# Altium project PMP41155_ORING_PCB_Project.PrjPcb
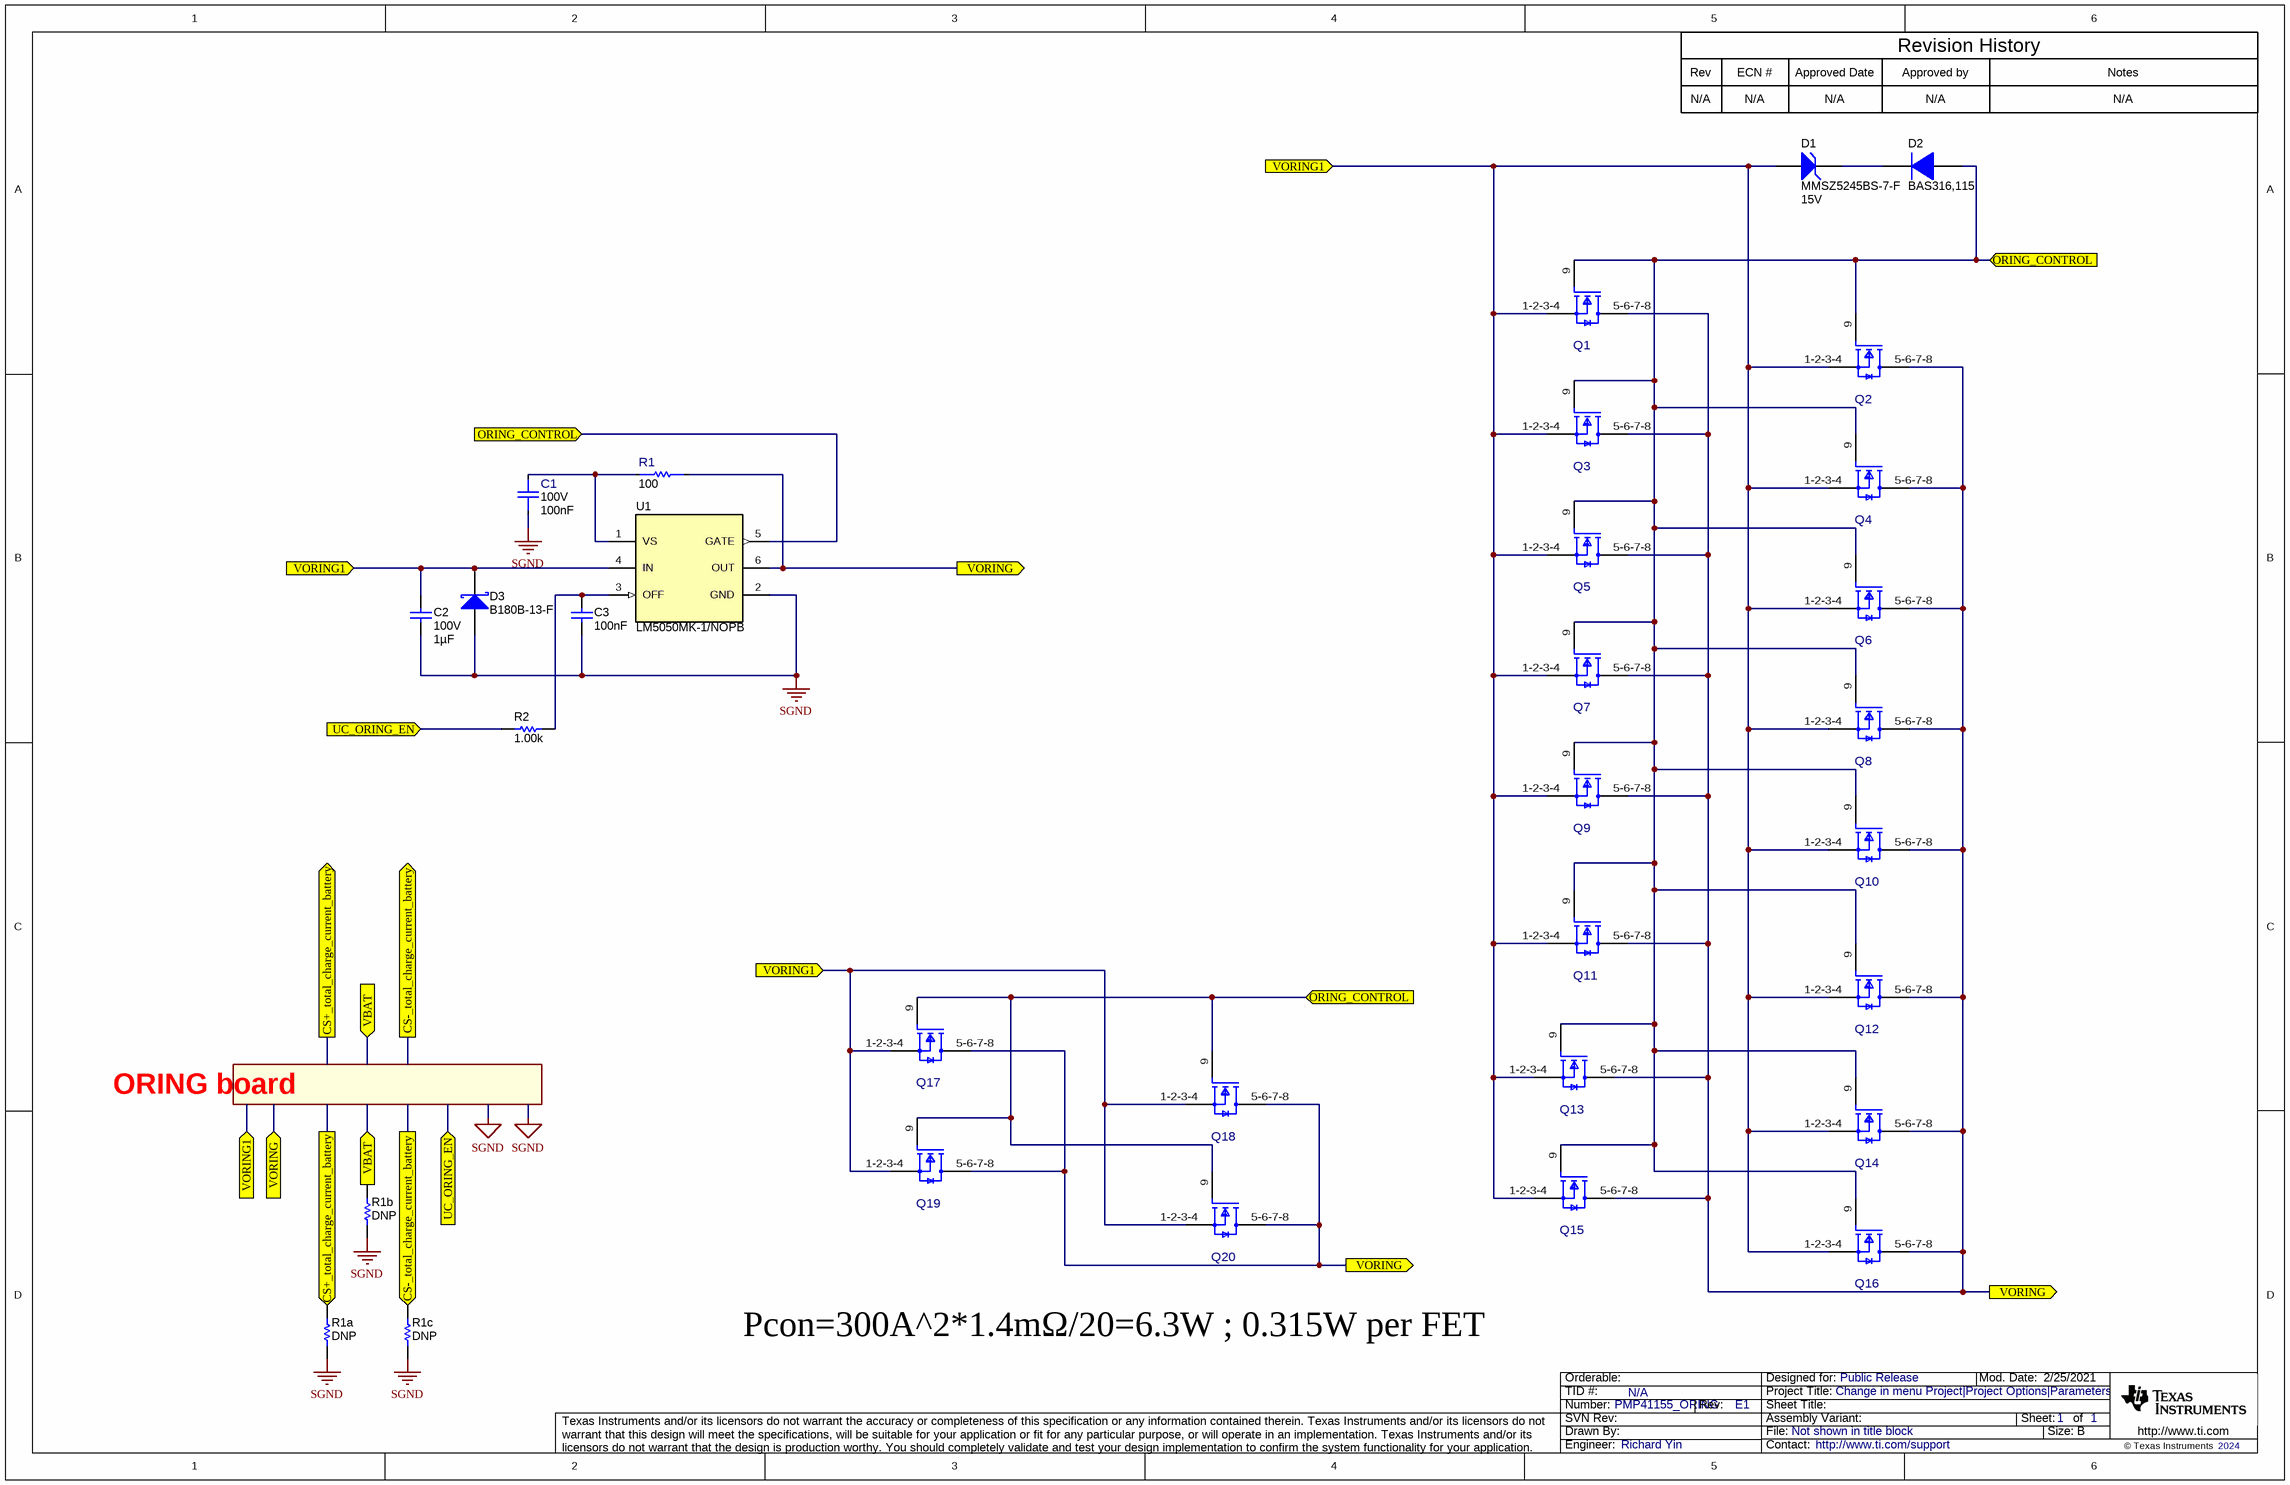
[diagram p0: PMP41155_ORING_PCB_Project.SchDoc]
CopyrightYear: 2024; PCB_Layout: Richard Yin; PCB_Rev: E1; PRJ_Customer: Public Release; PRJ_Engineer: Richard Yin; PRJ_Number: PMP41155_ORING; PRJ_Title: Change in menu Project|Project Options|Parameters; SCH_Rev: E1; TechSupport: http://www.ti.com/support; TID: N/A
1 sheet, 32 parts. Net scope: flat (ports and power ports of the same name join across sheets).
Board file: PMP41155_ORING_PCB_Project.PcbDoc

## Sheet PMP41155_ORING_PCB_Project.SchDoc
size 431 x 279 mm; Date: Not shown in title block; ApprovedBy: Not shown in title block; CheckedBy: Not shown in title block; Author: Not shown in title block; CompanyName: Not shown in title block; Engineer: Not shown in title block; Organization: Not shown in title block; Address1: Not shown in title block; Address2: Not shown in title block; Address3: Not shown in title block; Address4: Not shown in title block; DocumentNumber: 1; Revision: Use project parameter SCH_Rev; SheetNumber: 1; SheetTotal: 1; PageSetup: Record=PageOptions¦CenterHorizontal=True¦CenterVertical=True¦PrintScale=1.00¦XCorrection=1.00¦YCorrection=1.00¦PrintKind=0¦BorderSize=5000000¦LeftOffset=0¦BottomOffset=0¦Orientation=2¦PaperLength=1000¦PaperWidth=1000¦Scale=100¦PaperSource=15¦PrintQuality=600¦MediaType=1¦DitherType=10¦PaperKind=Letter¦PrintScaleMode=1

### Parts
C1  VDC_V: 100V  Cap_F: 100nF  [FP-885012206120_0603-MFG]  (hidden comment: 885012206120)
C2  VDC_V: 100V  Cap_F: 1µF  [0805_150]  (hidden comment: KAF21KR72A105KU)
C3  Cap_F: 100nF  [0603]  (hidden comment: GRM188R71E104KA01D)
D1  MMSZ5245BS-7-F  value 15V  [SOD-323]
D2  BAS316,115  [SOD-323]
D3  B180B-13-F  [SMB]
Q1  IQD016N08NM5CGATMA1  [FP-IQD016N08NM5CGATMA1_TTFN-9-MFG]  (value not drawn)
Q2  IQD016N08NM5CGATMA1  [FP-IQD016N08NM5CGATMA1_TTFN-9-MFG]  (value not drawn)
Q3  IQD016N08NM5CGATMA1  [FP-IQD016N08NM5CGATMA1_TTFN-9-MFG]  (value not drawn)
Q4  IQD016N08NM5CGATMA1  [FP-IQD016N08NM5CGATMA1_TTFN-9-MFG]  (value not drawn)
Q5  IQD016N08NM5CGATMA1  [FP-IQD016N08NM5CGATMA1_TTFN-9-MFG]  (value not drawn)
Q6  IQD016N08NM5CGATMA1  [FP-IQD016N08NM5CGATMA1_TTFN-9-MFG]  (value not drawn)
Q7  IQD016N08NM5CGATMA1  [FP-IQD016N08NM5CGATMA1_TTFN-9-MFG]  (value not drawn)
Q8  IQD016N08NM5CGATMA1  [FP-IQD016N08NM5CGATMA1_TTFN-9-MFG]  (value not drawn)
Q9  IQD016N08NM5CGATMA1  [FP-IQD016N08NM5CGATMA1_TTFN-9-MFG]  (value not drawn)
Q10  IQD016N08NM5CGATMA1  [FP-IQD016N08NM5CGATMA1_TTFN-9-MFG]  (value not drawn)
Q11  IQD016N08NM5CGATMA1  [FP-IQD016N08NM5CGATMA1_TTFN-9-MFG]  (value not drawn)
Q12  IQD016N08NM5CGATMA1  [FP-IQD016N08NM5CGATMA1_TTFN-9-MFG]  (value not drawn)
Q13  IQD016N08NM5CGATMA1  [FP-IQD016N08NM5CGATMA1_TTFN-9-MFG]  (value not drawn)
Q14  IQD016N08NM5CGATMA1  [FP-IQD016N08NM5CGATMA1_TTFN-9-MFG]  (value not drawn)
Q15  IQD016N08NM5CGATMA1  [FP-IQD016N08NM5CGATMA1_TTFN-9-MFG]  (value not drawn)
Q16  IQD016N08NM5CGATMA1  [FP-IQD016N08NM5CGATMA1_TTFN-9-MFG]  (value not drawn)
Q17  IQD016N08NM5CGATMA1  [FP-IQD016N08NM5CGATMA1_TTFN-9-MFG]  (value not drawn)
Q18  IQD016N08NM5CGATMA1  [FP-IQD016N08NM5CGATMA1_TTFN-9-MFG]  (value not drawn)
Q19  IQD016N08NM5CGATMA1  [FP-IQD016N08NM5CGATMA1_TTFN-9-MFG]  (value not drawn)
Q20  IQD016N08NM5CGATMA1  [FP-IQD016N08NM5CGATMA1_TTFN-9-MFG]  (value not drawn)
R1  value 100  [FP-RMCF0402FT100R_0402-MFG]  (hidden comment: RMCF0402FT100R)
R1a  ValueDisplayed: DNP  [0402]  (hidden comment: MCR01MZPF1001)
R1b  ValueDisplayed: DNP  [0402]  (hidden comment: MCR01MZPF1001)
R1c  ValueDisplayed: DNP  [0402]  (hidden comment: MCR01MZPF1001)
R2  ValueDisplayed: 1.00k  [0402]  (hidden comment: MCR01MZPF1001)
U1  LM5050MK-1/NOPB  [DDC0006A_N]

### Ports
CS+_total_charge_current_battery (out), CS-_total_charge_current_battery (out), ORING_CONTROL (in), UC_ORING_EN (in), VBAT (in), VORING1 (in), VORING (in), VORING (out)

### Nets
SGND: C1.1 C2.2 C3.2 D3.2(A) R1a.1 R1b.1 R1c.1 U1.2(GND)
CS+_total_charge_current_battery: R1a.2 ; port CS+_total_charge_current_battery
CS-_total_charge_current_battery: R1c.2 ; port CS-_total_charge_current_battery
ORING_CONTROL: D2.2(A) Q1.9(Gate) Q2.9(Gate) Q3.9(Gate) Q4.9(Gate) Q5.9(Gate) Q6.9(Gate) Q7.9(Gate) Q8.9(Gate) Q9.9(Gate) Q10.9(Gate) Q11.9(Gate) Q12.9(Gate) Q13.9(Gate) Q14.9(Gate) Q15.9(Gate) Q16.9(Gate) Q17.9(Gate) Q18.9(Gate) Q19.9(Gate) Q20.9(Gate) U1.5(GATE) ; port ORING_CONTROL
UC_ORING_EN: R2.1 ; port UC_ORING_EN
VBAT: R1b.2 ; port VBAT
VORING: Q1.5-6-7-8(Drain) Q2.5-6-7-8(Drain) Q3.5-6-7-8(Drain) Q4.5-6-7-8(Drain) Q5.5-6-7-8(Drain) Q6.5-6-7-8(Drain) Q7.5-6-7-8(Drain) Q8.5-6-7-8(Drain) Q9.5-6-7-8(Drain) Q10.5-6-7-8(Drain) Q11.5-6-7-8(Drain) Q12.5-6-7-8(Drain) Q13.5-6-7-8(Drain) Q14.5-6-7-8(Drain) Q15.5-6-7-8(Drain) Q16.5-6-7-8(Drain) Q17.5-6-7-8(Drain) Q18.5-6-7-8(Drain) Q19.5-6-7-8(Drain) Q20.5-6-7-8(Drain) R1.2 U1.6(OUT) ; port VORING
VORING1: C2.1 D1.2(A) D3.1(K) Q1.1-2-3-4(Source) Q2.1-2-3-4(Source) Q3.1-2-3-4(Source) Q4.1-2-3-4(Source) Q5.1-2-3-4(Source) Q6.1-2-3-4(Source) Q7.1-2-3-4(Source) Q8.1-2-3-4(Source) Q9.1-2-3-4(Source) Q10.1-2-3-4(Source) Q11.1-2-3-4(Source) Q12.1-2-3-4(Source) Q13.1-2-3-4(Source) Q14.1-2-3-4(Source) Q15.1-2-3-4(Source) Q16.1-2-3-4(Source) Q17.1-2-3-4(Source) Q18.1-2-3-4(Source) Q19.1-2-3-4(Source) Q20.1-2-3-4(Source) U1.4(IN) ; port VORING1
NetC1_2: C1.2 R1.1 U1.1(VS)
NetC3_1: C3.1 R2.2 U1.3(OFF)
NetD1_1: D1.1(K) D2.1(K)

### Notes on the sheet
- Rev
- N/A
- ECN #
- Approved Date
- Approved by
- Revision History
- Notes
- ORING board
- Pcon=300A^2*1.4mΩ/20=6.3W ; 0.315W per FET

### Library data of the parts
C1 = CMP-0097294-1: 0.1 µF ±10% 100V Ceramic Capacitor X7R 0603 (1608 Metric); Manufacturer: Wurth Electronics; TempCo: 15%; SizeZ_mm: 0.87mm; Value: 100nF; AEC Qualified: No
C2 = CMP-0861070-2: CAP, CERM, 1 µF, 100 V,+/- 10%, X7R, AEC-Q200 Grade 1, 0805; Manufacturer: AVX; SizeZ_mm: 1.5; Polarized: N; TaMax_C: 125°C; TaMin_C: -55°C; Value: 1uF; AEC Qualified: Y; U/M: EA; AEC Grade: 1; Cap_Case: 0805; SizeX_mm: 2; SizeArea_mm2: 2.5; SizeAreaWB_mm2: 6.75; AEC Category: Q200; SizeY_mm: 1.25
C3 = CMP-0007404-5: CAP, CERM, 0.1 uF, 25 V, +/- 10%, X7R, 0603; Manufacturer: MuRata; TaMin_C: -55°C; Polarized: N; SizeAreaWB_mm2: 4.68; Value1: Unknown; U/M: EA; Value: 0.1uF; TaMax_C: 125°C; SizeZ_mm: 1; SizeX_mm: 1.6; SizeY_mm: 0.8; Value2: 25V; SizeArea_mm2: 1.28; AEC Category: Q200; MFG_Status: TI_Obsolete
D1 = CMP-0005833-4: Diode, Zener, 15 V, 200 mW, SOD-323; Manufacturer: Diodes Inc.; SizeY_mm: 1.35; RJA_CperW: 350; SizeX_mm: 2.7; AEC Category: Q101; SizeAreaWB_mm2: 8.695; SizeZ_mm: 1; Power_W: 200mW; SizeArea_mm2: 3.645; Value1: 0.2W
D2 = CMP-0029006-2: Diode, Ultrafast, 100 V, 0.25 A, SOD-323; Manufacturer: Nexperia; SizeY_mm: 1.35; Value1: 0.25A; SizeAreaWB_mm2: 8.695; SizeZ_mm: 1; Io_A: 250mA; Value2: 1.4V; SizeX_mm: 2.7; Green_REACh: Incomplete; TJmax_C: 150°C; Green_Lifecycle: Not Set; Vr_V: 100V; AEC Category: Q101; Value: 100V; SizeArea_mm2: 3.645
D3 = CMP-0028394-2: Diode, Schottky, 80 V, 1 A, SMB; Manufacturer: Diodes Inc.; Value2: 0.79V; Value1: 1A; TJmax_C: 150°C; SizeY_mm: 3.81; SizeX_mm: 5.6; Green_REACh: Incomplete; Value: 80V; SizeZ_mm: 2.6; SizeArea_mm2: 21.336; Vf_V: 790mV; RJC_CperW: 25; Green_Lifecycle: Not Set; SizeAreaWB_mm2: 44.156; AEC Category: Q101
Q1-Q20 = CMP-0122332-1: N-Channel 80 V 31A (Ta), 323A (Tc) 3W (Ta), 333W (Tc) Surface Mount PG-TTFN-9-U02; Manufacturer: Infineon; AEC Qualified: No; QgTyp_nC: 106nC @ 10V; Rdson45_ohm: 1.4m; SizeZ_mm: 1.1mm; VdsMax_V: 1V; Vgs_V: 20V; ChMode: False; Drain To Source Breakdown Voltage: 80V; Input Capacitace At Vds: 7100pF @ 40V; Number Of Channels: 1; Pulse Drain Current: 1292A; Reverse Recovery Charge: 71nC; Reverse Recovery Time: 48ns; Rthja Max: 50°C/W; Threshold Vgs Max: 3.8V; Threshold Vgs Min: 2.2V; TJmax_C: +175°C; Transconductance: 140S; Turn Off Delay Time: 29ns; Turn On Delay Time: 15ns; Typ Forward Diode Voltage: 0.82V
R1 = CMP-0094733-1: 100Ω ±1% 0.063W 0402 Thick Film Chip Resistor AEC-Q200 compliant; Manufacturer: Stackpole Electronics; AEC Grade: Grade 0; Power_W: 63mW; TempCo: 100ppm/°C; VDC_V: 50V; SizeZ_mm: 0.35mm; AEC Qualified: Yes
R1a R1b R1c R2 = CMP-0026716-1: RES, 1.00 k, 1%, 0.063 W, 0402; Manufacturer: Rohm; Power_W: 63mW; TempCo: 100 ppm/C; Value_Code: 1k00; U/M: EA; Value: 1.00k; EIA_Code: E96; Res_ohm: 1k; SizeX_mm: 1; SizeY_mm: 0.5; SizeZ_mm: 0.6; Value2: 0.063W; AEC Qualified: N; VDC_V: 50V; AEC Category: Q200
U1 = CMP-0066129-2: High Side OR-ing FET Controller, DDC0006A (SOT-23-T-6); Manufacturer: Texas Instruments; SizeZ_mm: 0.87; SizeX_mm: 1.65; SizeY_mm: 2.95; SizeArea_mm2: 4.8675; CompType: IC; U/M: EA; SizeAreaWB_mm2: 10.4675

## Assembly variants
001: all parts fitted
